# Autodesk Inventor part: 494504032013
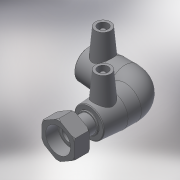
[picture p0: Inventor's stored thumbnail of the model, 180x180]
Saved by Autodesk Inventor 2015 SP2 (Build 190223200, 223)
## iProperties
Created: 2017-06
Part Number: 494504032013
Material: Generic
Description: PLASSON 90° ELBOW FEMALE FREE NUT TRANSITION 32-1.1/4"
Document SubType Name: Modeling
Designer: KIM
Mass: 55.0731 g
Surface Area: 148.067 cm^2
Volume: 55.0731 cm^3
Density: 1 g/cm^3
Appearance: Default
Author: KIM
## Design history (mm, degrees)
derived "494504.ipt"
feature "Solid1::494504.ipt"
tag "TaggingFeature1"
body "Solid1"
other parameters: "d2" = 44, "d4" = 27.66667, "d5" = 39.6, "d8" = 168 deg, "d10" = 16, "d11" = 5.33333, "d29" = 43, "d30" = 15, "d31" = 45.65, "d34" = 5 deg, "d41" = 4, "d42" = 14, "d43" = 0, "d48" = 61, "d49" = 32, "d50" = 27.2, "d51" = 16, "d54" = 90 deg, "d57" = 32, "d59" = 0, "d61" = 90 deg, "d86" = 3, "d87" = 0, "d97" = 23, "d98" = 36, "d99" = 58.428, "d109" = 0.96, "d116" = 18, "d117" = 38.952, "d118" = 14.4, "d119" = 1.44, "d120" = 31.1616, "d121" = 1.44, "d122" = 27.2664, "d123" = 23, "d124" = 1.9476, "d128" = 0, "d_" = 32, "L_" = 119, "D_" = 23, "A_" = 43, "d_2" = 12, "L_2" = 36, "D_1" = 44, "G_" = 38.952
